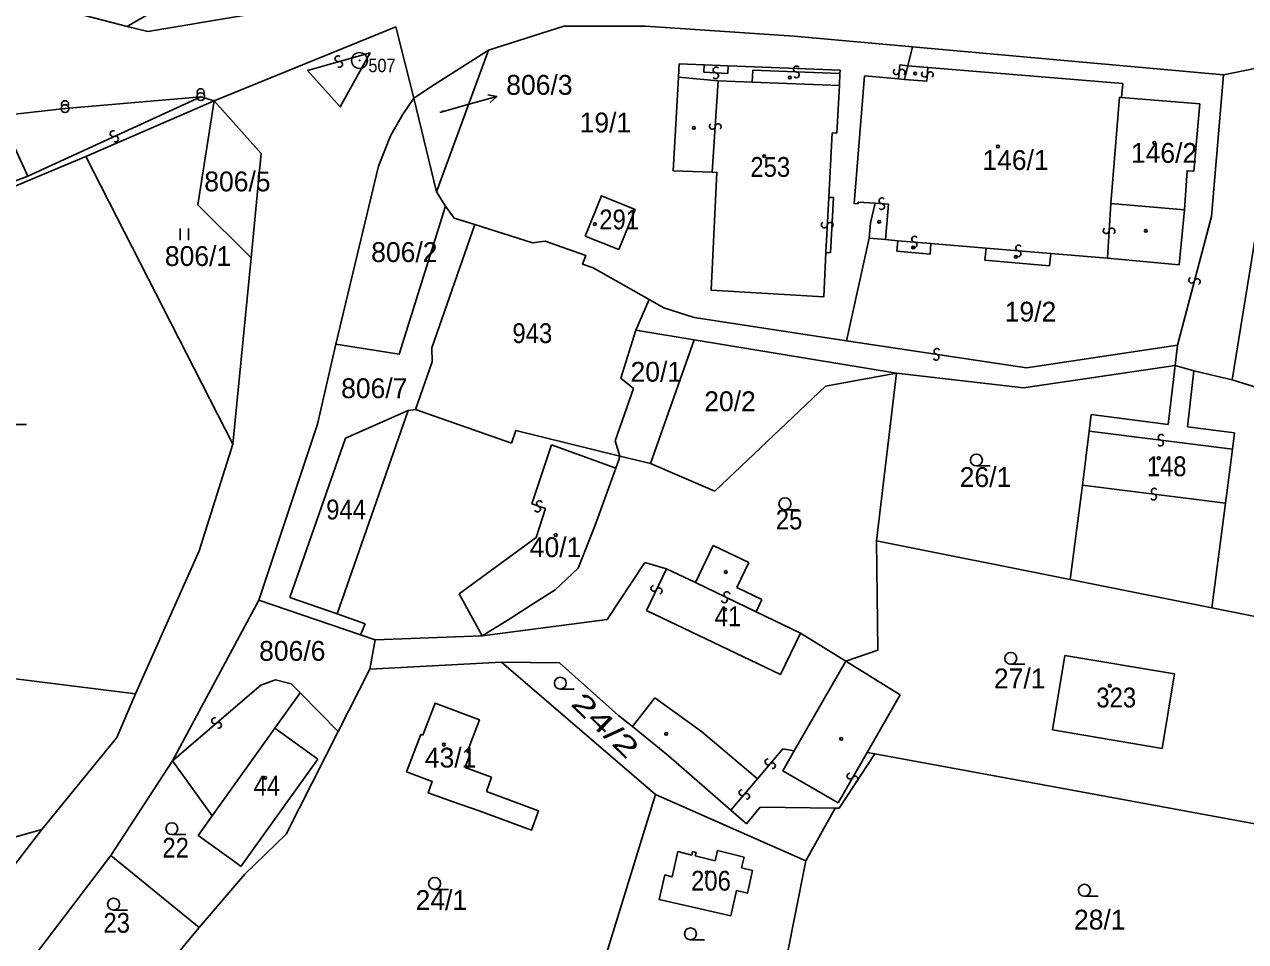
# Model space of a CAD drawing. Extents: x -680102 to -677253, y -1007548 to -1006096.
# Drawn here: x -679757 to -679602.9, y -1007197.5 to -1007081.9 of the extents above; entities that cross this region are included whole.
import ezdxf
from ezdxf.enums import TextEntityAlignment as Align

# ---------------------------------------------------------------- set-up
doc = ezdxf.new("R2010")
doc.units = 0
for name, color, linetype, lineweight in [('1', 7, 'Continuous', 25), ('16', 7, 'Continuous', 25), ('24', 7, 'Continuous', 25), ('25', 7, 'Continuous', 25), ('4', 7, 'Continuous', 25)]:
    doc.layers.add(name, color=color, linetype=linetype, lineweight=lineweight)
for name, color, linetype in [('17', 7, 'Continuous'), ('18', 7, 'Continuous'), ('19', 7, 'Continuous')]:
    doc.layers.add(name, color=color, linetype=linetype)

msp = doc.modelspace()

# ---------------------------------------------------------------- linework, layer by layer
at = {"layer": '1'}
for p, q in [((-679741.46, -1007082.75), (-679729.37, -1007080.74)), ((-679744.06, -1007082.12), (-679741.46, -1007082.75)), ((-679710.14, -1007082.19), (-679707.88, -1007091.16)), ((-679688.95, -1007082.1), (-679698.47, -1007085.12)), ((-679688.95, -1007082.1), (-679678.65, -1007082.1)), ((-679678.65, -1007082.1), (-679659.92, -1007083.35)), ((-679659.92, -1007083.35), (-679644.99, -1007084.71)), ((-679698.47, -1007085.12), (-679705.42, -1007089.52)), ((-679698.47, -1007085.12), (-679705.04, -1007102.97)), ((-679654.11, -1007087.64), (-679654.13, -1007088.07)), ((-679643.02, -1007087.3), (-679645.56, -1007087.08)), ((-679605.74, -1007088.23), (-679601.79, -1007087.43)), ((-679654.13, -1007088.07), (-679654.19, -1007089.59)), ((-679674.6, -1007090.05), (-679675.17, -1007100.32)), ((-679654.51, -1007095.58), (-679654.19, -1007089.59)), ((-679751.9, -1007092.49), (-679734.78, -1007090.98)), ((-679707.88, -1007091.16), (-679705.04, -1007102.97)), ((-679619.95, -1007104.46), (-679618.85, -1007091.06)), ((-679618.85, -1007091.06), (-679618.59, -1007091.08)), ((-679655.55, -1007103.68), (-679655.11, -1007095.55)), ((-679655.11, -1007095.55), (-679654.51, -1007095.58)), ((-679771.61, -1007107.84), (-679749.26, -1007098.51)), ((-679730.71, -1007134.81), (-679749.26, -1007098.51)), ((-679670.23, -1007100.51), (-679675.17, -1007100.32)), ((-679705.04, -1007102.97), (-679703.88, -1007104.77)), ((-679654.94, -1007103.71), (-679655.55, -1007103.68)), ((-679655.32, -1007110.68), (-679654.94, -1007103.71)), ((-679619.95, -1007104.46), (-679610.67, -1007105.23)), ((-679700.19, -1007107.12), (-679705.63, -1007122.67)), ((-679650.42, -1007108.84), (-679653.28, -1007121.75)), ((-679648.4, -1007109.01), (-679650.42, -1007108.84)), ((-679646.84, -1007109.14), (-679648.4, -1007109.01)), ((-679655.32, -1007110.68), (-679655.92, -1007110.65)), ((-679672.52, -1007121.63), (-679678.05, -1007137.24)), ((-679705.63, -1007122.67), (-679705.56, -1007124.4)), ((-679705.56, -1007124.4), (-679707.67, -1007130.44)), ((-679647.01, -1007125.85), (-679649.52, -1007147.01)), ((-679611.83, -1007124.87), (-679612.71, -1007132.31)), ((-679609.46, -1007125.57), (-679604.63, -1007126.67)), ((-679682.49, -1007134.38), (-679680.18, -1007127.8)), ((-679708.61, -1007130.56), (-679717.58, -1007156.21)), ((-679708.61, -1007130.56), (-679716.53, -1007134.04)), ((-679707.67, -1007130.44), (-679708.61, -1007130.56)), ((-679707.67, -1007130.44), (-679695.57, -1007134.66)), ((-679622.43, -1007131.08), (-679622.69, -1007133.15)), ((-679622.43, -1007131.08), (-679612.71, -1007132.31)), ((-679622.69, -1007133.15), (-679623.54, -1007139.96)), ((-679610.29, -1007132.61), (-679604.34, -1007133.37)), ((-679604.34, -1007133.37), (-679604.61, -1007135.44)), ((-679730.71, -1007134.81), (-679734.97, -1007148.27)), ((-679716.53, -1007134.04), (-679723.55, -1007154.13)), ((-679681.88, -1007136.3), (-679682.49, -1007134.38)), ((-679604.61, -1007135.44), (-679605.49, -1007142.24)), ((-679682.04, -1007136.77), (-679682.41, -1007137.82)), ((-679669.93, -1007140.72), (-679678.05, -1007137.24)), ((-679623.54, -1007139.96), (-679625.08, -1007151.88)), ((-679605.49, -1007142.24), (-679607.2, -1007155.44)), ((-679670.13, -1007147.56), (-679672.36, -1007152.26)), ((-679665.62, -1007149.72), (-679670.13, -1007147.56)), ((-679649.52, -1007147.01), (-679625.08, -1007151.88)), ((-679734.97, -1007148.27), (-679742.99, -1007166.28)), ((-679683.5, -1007156.89), (-679678.74, -1007149.71)), ((-679678.74, -1007149.71), (-679675.99, -1007150.51)), ((-679675.99, -1007150.51), (-679672.36, -1007152.26)), ((-679665.62, -1007149.72), (-679667.13, -1007152.88)), ((-679663.97, -1007154.39), (-679667.13, -1007152.88)), ((-679717.58, -1007156.21), (-679723.55, -1007154.13)), ((-679714.05, -1007157.44), (-679717.58, -1007156.21)), ((-679699.26, -1007158.98), (-679683.5, -1007156.89)), ((-679714.05, -1007157.44), (-679714.61, -1007158.83)), ((-679712.76, -1007159.46), (-679699.26, -1007158.98)), ((-679696.84, -1007162.3), (-679677.38, -1007178.96)), ((-679682.05, -1007169.01), (-679689.52, -1007162.36)), ((-679725.42, -1007170.6), (-679722.24, -1007166.14)), ((-679722.24, -1007166.14), (-679717.43, -1007171.04)), ((-679646.51, -1007166.42), (-679650.7, -1007173.67)), ((-679725.42, -1007170.6), (-679719.99, -1007174.53)), ((-679745.38, -1007171.78), (-679754.82, -1007183.38)), ((-679700.78, -1007173.81), (-679701.4, -1007175.56)), ((-679649.73, -1007173.85), (-679654.24, -1007180.72)), ((-679738.34, -1007174.74), (-679733.33, -1007181.65)), ((-679729.71, -1007188.05), (-679719.99, -1007174.53)), ((-679698.07, -1007176.78), (-679701.4, -1007175.56)), ((-679667.88, -1007180.97), (-679675.77, -1007174.12)), ((-679698.07, -1007176.78), (-679698.74, -1007178.61)), ((-679665.93, -1007182.66), (-679667.88, -1007180.97)), ((-679664.2, -1007180.57), (-679665.93, -1007182.66)), ((-679654.73, -1007180.69), (-679664.2, -1007180.57)), ((-679654.73, -1007180.69), (-679658.42, -1007187.35)), ((-679654.24, -1007180.72), (-679654.73, -1007180.69)), ((-679754.82, -1007183.38), (-679763.43, -1007194.48)), ((-679730.19, -1007187.7), (-679735.1, -1007184.13)), ((-679746.11, -1007186.68), (-679756.3, -1007200.04)), ((-679729.71, -1007188.05), (-679730.19, -1007187.7)), ((-679672.39, -1007186.72), (-679669.89, -1007187.36)), ((-679666.55, -1007188.21), (-679665.14, -1007188.57))]:
    msp.add_line(p, q, dxfattribs=at)
for points in [[(-679762.72, -1007077.25), (-679753.61, -1007079.63), (-679744.06, -1007082.12)], [(-679736.82, -1007077.98), (-679743.22, -1007081.64), (-679744.06, -1007082.12)], [(-679749.26, -1007098.51), (-679733.09, -1007091.51), (-679710.14, -1007082.19)], [(-679645.56, -1007087.08), (-679644.99, -1007084.71), (-679605.74, -1007088.23)], [(-679674.6, -1007090.05), (-679674.51, -1007088.52), (-679674.42, -1007086.83)], [(-679654.11, -1007087.64), (-679668.22, -1007087.08), (-679671.24, -1007086.96), (-679674.42, -1007086.83)], [(-679651.03, -1007088.36), (-679646.73, -1007088.74), (-679645.97, -1007088.8), (-679645.56, -1007087.08)], [(-679643.02, -1007087.3), (-679618.44, -1007089.32), (-679618.59, -1007091.08), (-679608.74, -1007091.9), (-679609.48, -1007100.39), (-679610.34, -1007100.32), (-679610.67, -1007105.23), (-679611.34, -1007112.18), (-679620.39, -1007111.35), (-679627.54, -1007110.77), (-679627.67, -1007112.3), (-679635.83, -1007111.61), (-679635.7, -1007110.08), (-679642.64, -1007109.49), (-679642.75, -1007110.83), (-679646.95, -1007110.47), (-679646.84, -1007109.14)], [(-679650.42, -1007108.84), (-679650.27, -1007106.87), (-679649.7, -1007104.42), (-679651.82, -1007104.29), (-679651.83, -1007104.49), (-679652.33, -1007104.46), (-679651.03, -1007088.36)], [(-679705.42, -1007089.52), (-679707.88, -1007091.16), (-679709.32, -1007093.26)], [(-679733.09, -1007091.51), (-679735.15, -1007104.63), (-679728.41, -1007111.29)], [(-679734.78, -1007090.98), (-679733.09, -1007091.51), (-679727.16, -1007098.15)], [(-679797.39, -1007097.55), (-679767.18, -1007094.19), (-679760.09, -1007093.4), (-679751.9, -1007092.49)], [(-679709.32, -1007093.26), (-679710.83, -1007095.92), (-679712.34, -1007099.74), (-679717.72, -1007122.18)], [(-679727.16, -1007098.15), (-679728.41, -1007111.29), (-679730.71, -1007134.81)], [(-679600.32, -1007100.05), (-679604.63, -1007126.67), (-679584.56, -1007132.96)], [(-679670.39, -1007115.38), (-679669.66, -1007100.54), (-679670.23, -1007100.51)], [(-679686.26, -1007108.55), (-679684.22, -1007103.48), (-679679.98, -1007105.2)], [(-679727.44, -1007154.46), (-679720.06, -1007132.29), (-679717.72, -1007122.18), (-679709.72, -1007123.47), (-679703.88, -1007104.77), (-679702.8, -1007106.3)], [(-679686.26, -1007108.55), (-679682.03, -1007110.27), (-679679.98, -1007105.2)], [(-679702.8, -1007106.3), (-679700.19, -1007107.12), (-679692.92, -1007109.42)], [(-679692.92, -1007109.42), (-679691.31, -1007109.22), (-679686.2, -1007110.99), (-679686.59, -1007112.12), (-679685.28, -1007112.57), (-679678.18, -1007116.57)], [(-679670.39, -1007115.38), (-679656.16, -1007116.21), (-679655.92, -1007110.65)], [(-679678.18, -1007116.57), (-679679.88, -1007120.41), (-679672.52, -1007121.63), (-679647.01, -1007125.85)], [(-679678.18, -1007116.57), (-679676.34, -1007117.62), (-679672.51, -1007118.81), (-679653.28, -1007121.75)], [(-679679.88, -1007120.41), (-679681.78, -1007126.47), (-679680.18, -1007127.8)], [(-679669.93, -1007140.72), (-679655.96, -1007127.5), (-679647.01, -1007125.85)], [(-679647.01, -1007125.85), (-679630.96, -1007127.71), (-679611.83, -1007124.87)], [(-679611.83, -1007124.87), (-679609.46, -1007125.57), (-679610.29, -1007132.61)], [(-679681.88, -1007136.3), (-679695.02, -1007133.08), (-679695.57, -1007134.66)], [(-679678.05, -1007137.24), (-679681.88, -1007136.3), (-679682.04, -1007136.77)], [(-679682.41, -1007137.82), (-679685.01, -1007145.01), (-679687.16, -1007150.42), (-679690.05, -1007153.17), (-679692.57, -1007154.76), (-679696.12, -1007157.02), (-679699.26, -1007158.98)], [(-679649.52, -1007147.01), (-679649.33, -1007160.76), (-679653.37, -1007162.18)], [(-679625.08, -1007151.88), (-679607.2, -1007155.44), (-679581.1, -1007160.64)], [(-679727.44, -1007154.46), (-679738.34, -1007174.74), (-679746.11, -1007186.68)], [(-679712.76, -1007159.46), (-679714.61, -1007158.83), (-679727.44, -1007154.46)], [(-679663.97, -1007154.39), (-679664.7, -1007155.94), (-679659.1, -1007158.64)], [(-679659.1, -1007158.64), (-679653.37, -1007162.18), (-679646.51, -1007166.42)], [(-679712.76, -1007159.46), (-679713.45, -1007163.19), (-679696.84, -1007162.3), (-679689.52, -1007162.36)], [(-679773.64, -1007162.47), (-679742.99, -1007166.28), (-679745.38, -1007171.78)], [(-679713.45, -1007163.19), (-679717.43, -1007171.04), (-679723.99, -1007183.99)], [(-679706.74, -1007171.5), (-679705.2, -1007167.47), (-679699.61, -1007169.58), (-679701.16, -1007173.66), (-679700.78, -1007173.81)], [(-679675.77, -1007174.12), (-679680.3, -1007170.42), (-679682.05, -1007169.01)], [(-679735.1, -1007184.13), (-679733.33, -1007181.65), (-679725.42, -1007170.6)], [(-679706.74, -1007171.5), (-679707.01, -1007171.4), (-679708.8, -1007176.14)], [(-679584.41, -1007185.88), (-679649.73, -1007173.85), (-679650.7, -1007173.67)], [(-679708.8, -1007176.14), (-679705.56, -1007177.36), (-679706.09, -1007178.77), (-679702.94, -1007179.91), (-679699.64, -1007181.04), (-679693.04, -1007183.47), (-679692.14, -1007181.04), (-679698.74, -1007178.61)], [(-679658.42, -1007187.35), (-679662.15, -1007205.98), (-679685.14, -1007204.06), (-679677.38, -1007178.96)], [(-679677.38, -1007178.96), (-679666.54, -1007183.76), (-679658.42, -1007187.35)], [(-679804.87, -1007197.41), (-679796.64, -1007195.1), (-679792.33, -1007193.89), (-679754.82, -1007183.38)], [(-679723.99, -1007183.99), (-679729.2, -1007189.01), (-679734.98, -1007195.76)], [(-679667.89, -1007194.28), (-679676.94, -1007192.21), (-679676.2, -1007189.13), (-679675.29, -1007189.35), (-679674.57, -1007186.17), (-679672.83, -1007186.61), (-679672.72, -1007186.18), (-679672.28, -1007186.29), (-679672.39, -1007186.72)], [(-679666.55, -1007188.21), (-679666.22, -1007186.9), (-679669.56, -1007186.05), (-679669.89, -1007187.36)], [(-679738.05, -1007199.47), (-679734.98, -1007195.76), (-679746.11, -1007186.68)], [(-679665.14, -1007188.57), (-679665.79, -1007191.41), (-679667.16, -1007191.1), (-679667.89, -1007194.28)]]:
    msp.add_lwpolyline(points, dxfattribs=at)
msp.add_lwpolyline([(-679625.74, -1007161.44), (-679611.93, -1007163.77), (-679613.49, -1007173.17), (-679627.33, -1007170.82)], close=True, dxfattribs=at)
at = {"layer": '16'}
for p, q in [((-679704.6, -1007092.98), (-679700.32, -1007091.76)), ((-679700.32, -1007091.76), (-679697.434, -1007090.944))]:
    msp.add_line(p, q, dxfattribs=at)
msp.add_lwpolyline([(-679698.532, -1007090.735), (-679697.434, -1007090.944), (-679698.26, -1007091.697)], dxfattribs=at)
at = {"layer": '24'}
for centre, radius in [((-679714.74, -1007086.41), 1), ((-679714.74, -1007086.41), 0.032), ((-679734.78, -1007090.98), 0.5), ((-679751.9, -1007092.49), 0.5), ((-679734.78, -1007090.98), 0.022), ((-679751.9, -1007092.49), 0.022)]:
    msp.add_circle(centre, radius, dxfattribs=at)
for centre in [(-679734.781, -1007090.417), (-679751.901, -1007091.927)]:
    msp.add_arc(centre, 0.437, 328.35109, 209.97456, dxfattribs=at)
at = {"layer": '25'}
for p, q in [((-679737.357, -1007109.095), (-679737.357, -1007107.595)), ((-679736.323, -1007109.095), (-679736.323, -1007107.595)), ((-679762.74, -1007132.3), (-679756.74, -1007132.3)), ((-679636.91, -1007137.55), (-679635.16, -1007137.55)), ((-679661.07, -1007143.07), (-679659.32, -1007143.07)), ((-679632.57, -1007162.56), (-679630.82, -1007162.56)), ((-679689.41, -1007165.69), (-679687.66, -1007165.69)), ((-679738.42, -1007184.04), (-679736.67, -1007184.04)), ((-679705.27, -1007190.95), (-679703.52, -1007190.95)), ((-679623.28, -1007191.8), (-679621.53, -1007191.8)), ((-679745.77, -1007193.56), (-679744.02, -1007193.56)), ((-679672.98, -1007197.3), (-679671.23, -1007197.3))]:
    msp.add_line(p, q, dxfattribs=at)
for centre, radius in [((-679660.46, -1007088.56), 0.175), ((-679644.64, -1007088.06), 0.175), ((-679672.55, -1007094.92), 0.175), ((-679614.46, -1007096.81), 0.175), ((-679663.68, -1007098.48), 0.175), ((-679634.19, -1007097.26), 0.175), ((-679685.06, -1007107.05), 0.175), ((-679649.18, -1007106.77), 0.175), ((-679615.54, -1007107.89), 0.175), ((-679644.88, -1007110.01), 0.175), ((-679631.93, -1007111.19), 0.175), ((-679636.91, -1007136.8), 0.75), ((-679613.91, -1007136.58), 0.175), ((-679661.07, -1007142.32), 0.75), ((-679689.99, -1007146.26), 0.175), ((-679668.54, -1007150.92), 0.175), ((-679668.63, -1007155.64), 0.175), ((-679632.57, -1007161.81), 0.75), ((-679689.41, -1007164.94), 0.75), ((-679620.08, -1007165.27), 0.175), ((-679704.09, -1007172.69), 0.175), ((-679676.04, -1007171.34), 0.175), ((-679653.98, -1007171.97), 0.175), ((-679726.66, -1007176.87), 0.175), ((-679738.42, -1007183.29), 0.75), ((-679705.27, -1007190.2), 0.75), ((-679670.93, -1007188.82), 0.175), ((-679623.28, -1007191.05), 0.75), ((-679745.77, -1007192.81), 0.75), ((-679672.98, -1007196.55), 0.75)]:
    msp.add_circle(centre, radius, dxfattribs=at)
for centre, radius, start, end in [((-679717.446, -1007086.195), 0.368, 53.02345, 285.13441), ((-679717.255, -1007086.906), 0.368, 232.94532, 104.89181), ((-679669.766, -1007087.612), 0.368, 34.38062, 266.02767), ((-679659.612, -1007087.493), 0.368, 34.73383, 267.19423), ((-679647.016, -1007087.823), 0.367, 122.19234, 354.23023), ((-679646.283, -1007087.898), 0.369, 302.13965, 174.09278), ((-679669.813, -1007088.347), 0.367, 214.2009, 86.41463), ((-679659.649, -1007088.228), 0.369, 215.07006, 87.04797), ((-679643.456, -1007088.138), 0.368, 122.80965, 355.00606), ((-679642.723, -1007088.204), 0.368, 302.70025, 174.94998), ((-679745.83, -1007095.653), 0.369, 61.83658, 293.71712), ((-679670.217, -1007094.721), 0.368, 123.82049, 355.48475), ((-679669.483, -1007094.777), 0.368, 303.14554, 175.79376), ((-679745.53, -1007096.326), 0.368, 241.72785, 114.05826), ((-679648.834, -1007104.103), 0.367, 33.72725, 265.94978), ((-679648.887, -1007104.837), 0.368, 213.95024, 85.79589), ((-679656.097, -1007107.147), 0.367, 124.32313, 356.41678), ((-679655.362, -1007107.194), 0.368, 304.38277, 176.27287), ((-679620.536, -1007107.884), 0.367, 123.91425, 355.93946), ((-679619.803, -1007107.938), 0.368, 303.82192, 176.02367), ((-679644.775, -1007109.677), 0.369, 212.69954, 84.79441), ((-679644.707, -1007108.944), 0.368, 32.64438, 264.85002), ((-679631.655, -1007110.797), 0.368, 212.4848, 84.41015), ((-679631.586, -1007110.064), 0.367, 32.55863, 264.69478), ((-679609.745, -1007114.112), 0.368, 112.66861, 344.3603), ((-679609.035, -1007114.307), 0.368, 292.30506, 164.71888), ((-679641.882, -1007123.107), 0.368, 28.63847, 260.92411), ((-679642, -1007123.834), 0.369, 208.72386, 80.71026), ((-679613.601, -1007133.936), 0.367, 30.01242, 262.33528), ((-679613.7, -1007134.665), 0.368, 210.11272, 82.04795), ((-679614.57, -1007141.465), 0.368, 210.32528, 82.04809), ((-679614.471, -1007140.736), 0.367, 30.16305, 262.33528), ((-679692.273, -1007142.987), 0.368, 198.48562, 70.48569), ((-679692.029, -1007142.293), 0.368, 18.41454, 250.77817), ((-679677.59, -1007152.975), 0.369, 101.43278, 333.21559), ((-679676.931, -1007153.303), 0.367, 281.09759, 153.64553), ((-679668.368, -1007153.77), 0.367, 11.48775, 243.8551), ((-679668.694, -1007154.43), 0.368, 191.58589, 63.74794), ((-679733.007, -1007169.689), 0.368, 77.79266, 310.1473), ((-679732.534, -1007170.253), 0.368, 257.92903, 130.16769), ((-679663.198, -1007174.868), 0.369, 87.04511, 318.96286), ((-679662.641, -1007175.35), 0.368, 266.49438, 139.29849), ((-679652.847, -1007176.662), 0.368, 97.49257, 329.33213), ((-679652.213, -1007177.035), 0.367, 277.23967, 149.73352), ((-679666.468, -1007178.738), 0.369, 87.04511, 318.96286), ((-679665.911, -1007179.22), 0.368, 266.49438, 139.29849)]:
    msp.add_arc(centre, radius, start, end, dxfattribs=at)
at = {"layer": '4'}
for p, q in [((-679671.29, -1007087.9), (-679671.24, -1007086.96)), ((-679668.28, -1007088.06), (-679668.22, -1007087.08)), ((-679665.13, -1007087.64), (-679665.21, -1007089.15)), ((-679665.13, -1007087.64), (-679654.13, -1007088.07)), ((-679646.73, -1007088.74), (-679646.57, -1007086.98)), ((-679645.56, -1007087.08), (-679646.57, -1007086.98)), ((-679643.16, -1007089.04), (-679643.02, -1007087.3)), ((-679669.48, -1007088.98), (-679674.51, -1007088.52)), ((-679668.28, -1007088.06), (-679671.29, -1007087.9)), ((-679669.48, -1007088.98), (-679670.23, -1007100.51)), ((-679669.48, -1007088.98), (-679665.21, -1007089.15)), ((-679665.21, -1007089.15), (-679654.19, -1007089.59)), ((-679645.97, -1007088.8), (-679643.16, -1007089.04)), ((-679605.74, -1007088.23), (-679607.26, -1007106.11)), ((-679655.92, -1007110.65), (-679655.55, -1007103.68)), ((-679620.39, -1007111.35), (-679619.95, -1007104.46)), ((-679607.26, -1007106.11), (-679611.52, -1007122.3)), ((-679646.84, -1007109.14), (-679642.64, -1007109.49)), ((-679635.7, -1007110.08), (-679627.54, -1007110.77)), ((-679622.69, -1007133.15), (-679604.61, -1007135.44)), ((-679693.02, -1007142.34), (-679690.51, -1007134.88)), ((-679682.41, -1007137.82), (-679690.51, -1007134.88)), ((-679623.54, -1007139.96), (-679605.49, -1007142.24)), ((-679675.99, -1007150.51), (-679678.52, -1007155.76)), ((-679672.36, -1007152.26), (-679664.7, -1007155.94)), ((-679661.62, -1007163.86), (-679678.52, -1007155.76)), ((-679659.1, -1007158.64), (-679661.62, -1007163.86)), ((-679659.89, -1007173.47), (-679653.37, -1007162.18)), ((-679680.3, -1007170.42), (-679677.49, -1007166.77)), ((-679677.49, -1007166.77), (-679671.61, -1007171.03)), ((-679671.61, -1007171.03), (-679664.51, -1007176.99)), ((-679661.33, -1007173.23), (-679664.51, -1007176.99)), ((-679661.35, -1007176.01), (-679659.89, -1007173.47)), ((-679659.89, -1007173.47), (-679661.33, -1007173.23)), ((-679650.7, -1007173.67), (-679654.36, -1007180.02)), ((-679664.51, -1007176.99), (-679667.88, -1007180.97)), ((-679661.35, -1007176.01), (-679654.36, -1007180.02))]:
    msp.add_line(p, q, dxfattribs=at)
for points in [[(-679756.57, -1007101), (-679760.09, -1007093.4), (-679764.49, -1007083.92)], [(-679734.78, -1007090.98), (-679756.57, -1007101), (-679762.95, -1007103.4), (-679771.63, -1007106.59), (-679796.56, -1007105.54)], [(-679649.7, -1007104.42), (-679648.02, -1007104.52), (-679648.4, -1007109.01)], [(-679653.28, -1007121.75), (-679630.6, -1007125.18), (-679611.52, -1007122.3), (-679611.83, -1007124.87)], [(-679693.02, -1007142.34), (-679691.28, -1007142.93), (-679692.47, -1007146.59), (-679702.15, -1007153.69), (-679699.26, -1007158.98)], [(-679738.34, -1007174.74), (-679727.2, -1007165.19), (-679725.36, -1007164.52), (-679723.35, -1007165.01), (-679722.24, -1007166.14)]]:
    msp.add_lwpolyline(points, dxfattribs=at)
msp.add_lwpolyline([(-679721.3, -1007087.66), (-679713.4, -1007085.44), (-679717.17, -1007092.28)], close=True, dxfattribs=at)

# ---------------------------------------------------------------- texts
at = {"layer": '16'}
msp.add_text('806/3', height=2.5, dxfattribs=at).set_placement((-679696.23, -1007090.74))
at = {"layer": '17', "width": 0.9}
msp.add_text('507', height=1.7, dxfattribs=at).set_placement((-679710.2, -1007087.89), align=Align.RIGHT)
at = {"layer": '18'}
for s, height, p in [('806/3', 0.1, (-679704.4, -1007092.78)), ('19/1', 2.5, (-679686.97, -1007095.49)), ('806/5', 2.5, (-679734.33, -1007102.92)), ('806/2', 2.5, (-679713.27, -1007111.83)), ('806/1', 2.5, (-679739.3, -1007112.33)), ('19/2', 2.5, (-679633.34, -1007119.34)), ('26/1', 2.5, (-679639.02, -1007140.2)), ('806/6', 2.5, (-679727.41, -1007162.12)), ('27/1', 2.5, (-679634.7, -1007165.59)), ('24/1', 2.5, (-679707.67, -1007193.54)), ('28/1', 2.5, (-679624.6, -1007196.01))]:
    msp.add_text(s, height=height, dxfattribs=at).set_placement(p)
at = {"layer": '18', "width": 0.9}
for s, p in [('943', (-679692.939, -1007122.05)), ('944', (-679716.439, -1007144.29))]:
    msp.add_text(s, height=2.5, dxfattribs=at).set_placement(p, align=Align.CENTER)
at = {"layer": '18'}
for s, p in [('20/1', (-679677.3, -1007126.92)), ('806/7', (-679712.88, -1007129)), ('20/2', (-679668, -1007130.64))]:
    msp.add_text(s, height=2.5, dxfattribs=at).set_placement(p, align=Align.CENTER)
at = {"layer": '18', "width": 0.9}
for s, p in [('25', (-679662.22, -1007145.56)), ('22', (-679739.61, -1007186.94)), ('23', (-679747.05, -1007196.41))]:
    msp.add_text(s, height=2.5, dxfattribs=at).set_placement(p)
at = {"layer": '18', "width": 1.55}
msp.add_text('24/2', height=2.5, rotation=316.003, dxfattribs=at).set_placement((-679688.228, -1007167.646))
at = {"layer": '19'}
for s, p in [('146/2', (-679617.42, -1007099.32)), ('146/1', (-679636.16, -1007100.22)), ('43/1', (-679706.5, -1007175.58))]:
    msp.add_text(s, height=2.5, dxfattribs=at).set_placement(p)
at = {"layer": '19', "width": 0.9}
for s, p in [('253', (-679665.43, -1007101.09)), ('291', (-679684.49, -1007107.71)), ('148', (-679615.42, -1007138.84)), ('41', (-679669.94, -1007157.76)), ('323', (-679621.78, -1007168)), ('44', (-679728.11, -1007179.12)), ('206', (-679672.91, -1007191.1))]:
    msp.add_text(s, height=2.5, dxfattribs=at).set_placement(p)
at = {"layer": '19'}
msp.add_text('40/1', height=2.5, dxfattribs=at).set_placement((-679690.01, -1007149.04), align=Align.CENTER)

doc.saveas('drawing.dxf')
